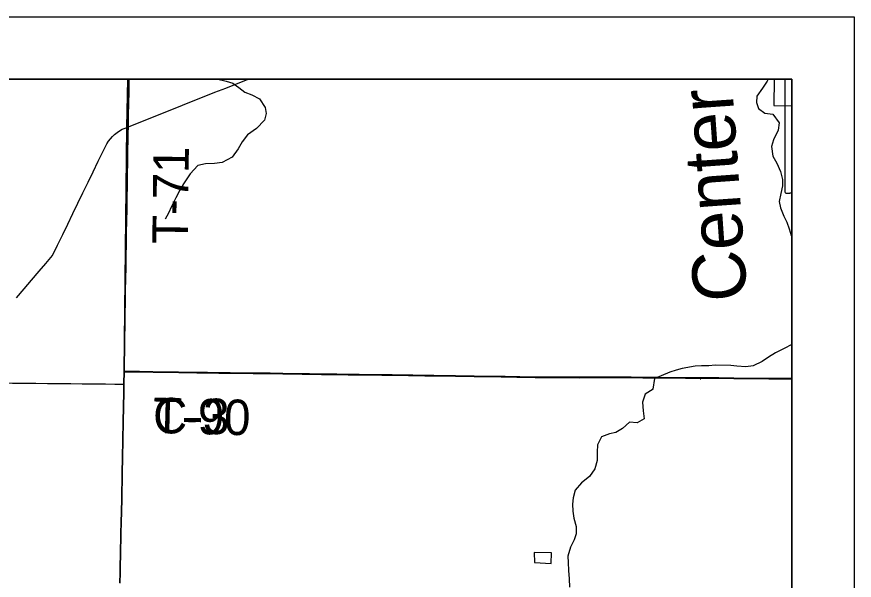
# Model space of a CAD drawing. Extents: x 0 to 34, y 0 to 22.
# Drawn here: x 7.658 to 9, y 20.097 to 21 of the extents above; entities that cross this region are included whole.
import ezdxf

# ---------------------------------------------------------------- set-up
doc = ezdxf.new("R2010")
doc.units = 0
for name, color, linetype in [('GM_X_Corporation', 7, 'Continuous'), ('GM_X_County_Road', 7, 'Continuous'), ('GM_X_County_Road_Text', 7, 'Continuous'), ('GM_X_Minor_Lake', 7, 'Continuous'), ('GM_X_Minor_River', 7, 'Continuous'), ('GM_X_Minor_River_Text', 7, 'Continuous'), ('GM_X_State_Shield', 7, 'Continuous'), ('GM_X_Township_Road', 7, 'Continuous'), ('GM_X_Township_Road_Text', 7, 'Continuous'), ('SH_Data', 7, 'Continuous')]:
    doc.layers.add(name, color=color, linetype=linetype)

msp = doc.modelspace()

# ---------------------------------------------------------------- linework, layer by layer
at = {"layer": 'GM_X_Corporation'}
for points in [[(7.8235, 20.0928), (7.8238, 20.1089), (7.8241, 20.1219), (7.8245, 20.1369), (7.825, 20.1729), (7.8253, 20.189), (7.8263, 20.2263), (7.827, 20.2692), (7.8275, 20.2934), (7.8288, 20.3506), (7.8296, 20.3984), (7.8298, 20.4118), (7.8301, 20.4313), (7.8546, 20.4315), (7.8763, 20.4311), (7.9174, 20.4306), (7.9465, 20.4301), (7.9639, 20.4298), (8, 20.4291), (8.0366, 20.4288), (8.064, 20.4286), (8.0845, 20.4283), (8.1274, 20.4276), (8.1709, 20.4271), (8.2069, 20.4266), (8.2597, 20.4261), (8.3262, 20.4252), (8.361, 20.4247), (8.3908, 20.4242), (8.4405, 20.4234), (8.4884, 20.4226), (8.5269, 20.4224), (8.5374, 20.4223), (8.5592, 20.4222), (8.5809, 20.4223), (8.6145, 20.4223), (8.6424, 20.4222), (8.7294, 20.4215), (8.7481, 20.4213), (8.7711, 20.4213), (8.7829, 20.4212), (8.8071, 20.421), (8.863, 20.4205), (8.8835, 20.4202), (8.9, 20.4201), (8.9, 20.9), (2.1, 20.9)], [(7.8235, 20.0928), (7.8238, 20.1089), (7.8241, 20.1219), (7.8245, 20.1369), (7.825, 20.1729), (7.8253, 20.189), (7.8263, 20.2263), (7.827, 20.2692), (7.8275, 20.2934), (7.8288, 20.3506), (7.8296, 20.3984), (7.8298, 20.4118), (7.8301, 20.4313), (7.8345, 20.8231), (7.8362, 20.9), (2.1, 20.9)], [(8.9, 14.1), (8.9, 20.4201), (8.8835, 20.4202), (8.863, 20.4205), (8.8071, 20.421), (8.7829, 20.4212), (8.7711, 20.4213), (8.7481, 20.4213), (8.7294, 20.4215), (8.6424, 20.4222), (8.6145, 20.4223), (8.5809, 20.4223), (8.5592, 20.4222), (8.5374, 20.4223), (8.5269, 20.4224), (8.4884, 20.4226), (8.4405, 20.4234), (8.3908, 20.4242), (8.361, 20.4247), (8.3262, 20.4252), (8.2597, 20.4261), (8.2069, 20.4266), (8.1709, 20.4271), (8.1274, 20.4276), (8.0845, 20.4283), (8.064, 20.4286), (8.0366, 20.4288), (8, 20.4291), (7.9639, 20.4298), (7.9465, 20.4301), (7.9174, 20.4306), (7.8763, 20.4311), (7.8546, 20.4315), (7.8301, 20.4313), (7.8298, 20.4118), (7.8296, 20.3984), (7.8288, 20.3506), (7.8275, 20.2934), (7.827, 20.2692), (7.8263, 20.2263), (7.8253, 20.189), (7.825, 20.1729), (7.8245, 20.1369), (7.8241, 20.1219), (7.8238, 20.1089), (7.8235, 20.0928)], [(8.9, 16.4207), (8.9, 20.4201), (8.8835, 20.4202), (8.863, 20.4205), (8.8071, 20.421), (8.7829, 20.4212), (8.7711, 20.4213), (8.7481, 20.4213), (8.7294, 20.4215), (8.6424, 20.4222), (8.6145, 20.4223), (8.5809, 20.4223), (8.5592, 20.4222), (8.5374, 20.4223), (8.5269, 20.4224), (8.4884, 20.4226), (8.4405, 20.4234), (8.3908, 20.4242), (8.361, 20.4247), (8.3262, 20.4252), (8.2597, 20.4261), (8.2069, 20.4266), (8.1709, 20.4271), (8.1274, 20.4276), (8.0845, 20.4283), (8.064, 20.4286), (8.0366, 20.4288), (8, 20.4291), (7.9639, 20.4298), (7.9465, 20.4301), (7.9174, 20.4306), (7.8763, 20.4311), (7.8546, 20.4315), (7.8301, 20.4313), (7.8298, 20.4118), (7.8296, 20.3984), (7.8288, 20.3506), (7.8275, 20.2934), (7.827, 20.2692), (7.8263, 20.2263), (7.8253, 20.189), (7.825, 20.1729), (7.8245, 20.1369), (7.8241, 20.1219), (7.8238, 20.1089), (7.8235, 20.0928)]]:
    msp.add_lwpolyline(points, dxfattribs=at)
for points in [[(8.9, 20.4201), (8.9, 20.9), (7.8362, 20.9), (7.8345, 20.8231), (7.8301, 20.4313), (7.8546, 20.4315), (7.8763, 20.4311), (7.9174, 20.4306), (7.9465, 20.4301), (7.9639, 20.4298), (8, 20.4291), (8.0366, 20.4288), (8.064, 20.4286), (8.0845, 20.4283), (8.1274, 20.4276), (8.1709, 20.4271), (8.2069, 20.4266), (8.2597, 20.4261), (8.3262, 20.4252), (8.361, 20.4247), (8.3908, 20.4242), (8.4405, 20.4234), (8.4884, 20.4226), (8.5269, 20.4224), (8.5374, 20.4223), (8.5592, 20.4222), (8.5809, 20.4223), (8.6145, 20.4223), (8.6424, 20.4222), (8.7294, 20.4215), (8.7481, 20.4213), (8.7711, 20.4213), (8.7829, 20.4212), (8.8071, 20.421), (8.863, 20.4205), (8.8835, 20.4202)], [(8.9, 20.8573), (8.9, 20.9), (8.8716, 20.9), (8.8709, 20.8576)]]:
    msp.add_lwpolyline(points, close=True, dxfattribs=at)
at = {"layer": 'GM_X_County_Road'}
msp.add_line((8.391, 20.4237), (8.4091, 20.4234), dxfattribs=at)
for points in [[(7.8371, 20.8238), (7.8544, 20.8307), (7.8717, 20.8376), (7.889, 20.8444), (7.9064, 20.8513), (7.9237, 20.8582), (7.941, 20.8651), (7.9583, 20.872), (7.9756, 20.8789), (7.9929, 20.8858), (8.0103, 20.8927), (8.0276, 20.8996), (8.0286, 20.9)], [(7.6577, 20.5497), (7.6698, 20.5639), (7.6819, 20.578), (7.694, 20.5922), (7.7048, 20.6048), (7.7155, 20.6174), (7.7237, 20.6341), (7.7318, 20.6509), (7.7399, 20.6677), (7.748, 20.6845), (7.7561, 20.7012), (7.7643, 20.718), (7.7724, 20.7348), (7.7805, 20.7516), (7.7886, 20.7684), (7.7944, 20.7803), (7.8002, 20.7922), (7.8025, 20.7965), (7.8051, 20.8007), (7.8081, 20.8046), (7.8114, 20.8082), (7.815, 20.8115), (7.8189, 20.8146), (7.823, 20.8173), (7.8273, 20.8197), (7.8318, 20.8217), (7.8371, 20.8238)], [(7.8301, 20.4113), (7.8302, 20.421), (7.8304, 20.4307)], [(7.8304, 20.4307), (7.8548, 20.4309), (7.8657, 20.4307), (7.8766, 20.4305), (7.9064, 20.4302), (7.9176, 20.4301), (7.9322, 20.4298), (7.9468, 20.4295), (7.9642, 20.4293), (7.9822, 20.4289), (8.0002, 20.4286), (8.0369, 20.4283), (8.0505, 20.4282), (8.0642, 20.4281), (8.0847, 20.4277), (8.1034, 20.4275), (8.1155, 20.4273), (8.1276, 20.4271), (8.1462, 20.4269), (8.1587, 20.4267), (8.1711, 20.4266), (8.1891, 20.4263), (8.2071, 20.4261), (8.2258, 20.4259), (8.2429, 20.4257), (8.2599, 20.4255), (8.3118, 20.4248), (8.3438, 20.4244), (8.3612, 20.4241), (8.391, 20.4237)], [(8.4091, 20.4234), (8.4594, 20.4226), (8.474, 20.4223), (8.4886, 20.4221), (8.5072, 20.422), (8.5172, 20.4219), (8.5377, 20.4218), (8.5485, 20.4217), (8.5594, 20.4216), (8.5811, 20.4218), (8.6613, 20.4215), (8.6986, 20.4212), (8.7297, 20.421), (8.7483, 20.4208), (8.7831, 20.4207), (8.8073, 20.4204), (8.8446, 20.4201), (8.8632, 20.4199), (8.8837, 20.4197), (8.9, 20.4196)], [(7.8238, 20.0922), (7.8241, 20.1084), (7.8244, 20.1214), (7.8247, 20.1363), (7.825, 20.1543), (7.8252, 20.1724), (7.8255, 20.1885), (7.8261, 20.2071), (7.8263, 20.2164), (7.8266, 20.2258), (7.8273, 20.2687), (7.8277, 20.2929), (7.8282, 20.3115), (7.8286, 20.3301), (7.829, 20.35), (7.8293, 20.3687), (7.8296, 20.3833), (7.8298, 20.3979), (7.8301, 20.4113)]]:
    msp.add_lwpolyline(points, dxfattribs=at)
at = {"layer": 'GM_X_Minor_Lake'}
for points in [[(8.5149, 20.1407), (8.487, 20.1412), (8.4877, 20.1252)], [(8.4877, 20.1252), (8.5145, 20.1239), (8.5149, 20.1407), (8.5149, 20.1407)]]:
    msp.add_lwpolyline(points, dxfattribs=at)
at = {"layer": 'GM_X_Minor_River'}
msp.add_line((8.6778, 20.403), (8.6806, 20.4203), dxfattribs=at)
for points in [[(7.9788, 20.9), (7.9803, 20.8999), (7.9939, 20.8965), (8.0041, 20.8936), (8.0141, 20.8865), (8.0238, 20.879), (8.0347, 20.8749), (8.047, 20.8682), (8.0562, 20.8543), (8.0578, 20.8447), (8.0549, 20.8342), (8.0424, 20.8208), (8.0277, 20.811), (8.0194, 20.7998), (8.0127, 20.7882), (8.0032, 20.7748), (7.9874, 20.7665), (7.9749, 20.7649), (7.9608, 20.7645), (7.9482, 20.7618), (7.9361, 20.7485), (7.9251, 20.7324), (7.9195, 20.722), (7.9131, 20.7096), (7.9063, 20.6961), (7.9011, 20.6853), (7.8959, 20.6755)], [(8.8623, 20.9), (8.8605, 20.8968), (8.8529, 20.8856), (8.8439, 20.8726), (8.8432, 20.8627), (8.8464, 20.8532), (8.8568, 20.8457), (8.8697, 20.8438), (8.8799, 20.8299), (8.8781, 20.8182), (8.8705, 20.8025), (8.8675, 20.7923), (8.8698, 20.7767), (8.8759, 20.7651), (8.882, 20.7521), (8.8851, 20.7391), (8.8852, 20.7288), (8.8826, 20.7168), (8.8796, 20.7039), (8.882, 20.6936), (8.8874, 20.6806), (8.892, 20.6706), (8.8959, 20.6603), (8.899, 20.6492), (8.9, 20.6453)], [(8.9, 20.475), (8.8878, 20.4685), (8.8736, 20.4612), (8.8628, 20.4547), (8.8523, 20.4474), (8.8378, 20.4405), (8.8263, 20.4389), (8.8119, 20.44), (8.8021, 20.4411), (8.7771, 20.4417), (8.7668, 20.4408), (8.7554, 20.4407), (8.7452, 20.4399), (8.7242, 20.4362), (8.7147, 20.4338), (8.7043, 20.4303), (8.6806, 20.4201)], [(8.754, 20.4193), (8.7533, 20.4191)], [(8.6778, 20.403), (8.6651, 20.3952), (8.661, 20.3824), (8.6619, 20.3687), (8.6632, 20.3557), (8.6524, 20.3495), (8.6398, 20.3505), (8.6285, 20.3404), (8.6181, 20.3338), (8.6081, 20.3317), (8.5951, 20.327), (8.5884, 20.3142), (8.5881, 20.3024), (8.5883, 20.2891), (8.5846, 20.2755), (8.5759, 20.2635), (8.5628, 20.2531), (8.553, 20.2411), (8.5497, 20.229), (8.5488, 20.2191), (8.5493, 20.2077), (8.5506, 20.1963), (8.5546, 20.1829), (8.5547, 20.1715), (8.5511, 20.1616), (8.5456, 20.15), (8.5411, 20.1356), (8.5417, 20.1253), (8.5422, 20.1124), (8.5435, 20.0994), (8.544, 20.0857)]]:
    msp.add_lwpolyline(points, dxfattribs=at)
at = {"layer": 'GM_X_State_Shield'}
msp.add_lwpolyline([(8.9, 20.717), (8.9, 20.9), (8.8889, 20.9), (8.8889, 20.7206)], dxfattribs=at)
for centre, radius, start, end in [((8.892, 20.7201), 0.00308, 171.4911, 258.3065), ((8.8925, 20.7406), 0.0235, 267.339, 280.6039), ((8.8973, 20.709), 0.00848, 71.2569, 93.2717)]:
    msp.add_arc(centre, radius, start, end, dxfattribs=at)
at = {"layer": 'GM_X_Township_Road'}
msp.add_line((8.391, 20.4237), (8.4091, 20.4234), dxfattribs=at)
for points in [[(7.8304, 20.4307), (7.8307, 20.4494), (7.831, 20.468), (7.8313, 20.4867), (7.8316, 20.5053), (7.832, 20.5239), (7.8323, 20.5426), (7.8326, 20.5612), (7.8329, 20.5799), (7.8332, 20.5985), (7.8336, 20.6171), (7.8339, 20.6358), (7.8342, 20.6544), (7.8345, 20.6731), (7.8348, 20.6917), (7.8351, 20.7104), (7.8355, 20.729), (7.8358, 20.7476), (7.8361, 20.7663), (7.8364, 20.7849), (7.8367, 20.8036), (7.8369, 20.8137), (7.8371, 20.8238), (7.8374, 20.8424), (7.8377, 20.8611), (7.8381, 20.8797), (7.8384, 20.897), (7.8384, 20.9)], [(7.8301, 20.4113), (7.8302, 20.421), (7.8304, 20.4307)], [(7.8304, 20.4307), (7.8548, 20.4309), (7.8657, 20.4307), (7.8766, 20.4305), (7.9064, 20.4302), (7.9176, 20.4301), (7.9322, 20.4298), (7.9468, 20.4295), (7.9642, 20.4293), (7.9822, 20.4289), (8.0002, 20.4286), (8.0369, 20.4283), (8.0505, 20.4282), (8.0642, 20.4281), (8.0847, 20.4277), (8.1034, 20.4275), (8.1155, 20.4273), (8.1276, 20.4271), (8.1462, 20.4269), (8.1587, 20.4267), (8.1711, 20.4266), (8.1891, 20.4263), (8.2071, 20.4261), (8.2258, 20.4259), (8.2429, 20.4257), (8.2599, 20.4255), (8.3118, 20.4248), (8.3438, 20.4244), (8.3612, 20.4241), (8.391, 20.4237)], [(8.4091, 20.4234), (8.4594, 20.4226), (8.474, 20.4223), (8.4886, 20.4221), (8.5072, 20.422), (8.5172, 20.4219), (8.5377, 20.4218), (8.5485, 20.4217), (8.5594, 20.4216), (8.5811, 20.4218), (8.6613, 20.4215), (8.6986, 20.4212), (8.7297, 20.421), (8.7483, 20.4208), (8.7831, 20.4207), (8.8073, 20.4204), (8.8446, 20.4201), (8.8632, 20.4199), (8.8837, 20.4197), (8.9, 20.4196)], [(7.5413, 20.4141), (7.5591, 20.4139), (7.5768, 20.4137), (7.5955, 20.4135), (7.6141, 20.4133), (7.6327, 20.4132), (7.6514, 20.413), (7.67, 20.4128), (7.6887, 20.4126), (7.7073, 20.4125), (7.7259, 20.4123), (7.7446, 20.4121), (7.7632, 20.4119), (7.7819, 20.4117), (7.8005, 20.4116), (7.8153, 20.4114), (7.8301, 20.4113)], [(7.8238, 20.0922), (7.8241, 20.1084), (7.8244, 20.1214), (7.8247, 20.1363), (7.825, 20.1543), (7.8252, 20.1724), (7.8255, 20.1885), (7.8261, 20.2071), (7.8263, 20.2164), (7.8266, 20.2258), (7.8273, 20.2687), (7.8277, 20.2929), (7.8282, 20.3115), (7.8286, 20.3301), (7.829, 20.35), (7.8293, 20.3687), (7.8296, 20.3833), (7.8298, 20.3979), (7.8301, 20.4113)]]:
    msp.add_lwpolyline(points, dxfattribs=at)
at = {"layer": 'SH_Data'}
for p, q in [((2, 21), (9, 21)), ((9, 21), (9, 14)), ((2.1, 20.9), (8.9, 20.9)), ((2.1, 20.9), (8.9, 20.9)), ((8.9, 20.9), (8.9, 14.1)), ((8.9, 20.9), (8.9, 14.1))]:
    msp.add_line(p, q, dxfattribs=at)

# ---------------------------------------------------------------- texts
at = {"layer": 'GM_X_County_Road_Text'}
msp.add_text('C-3', height=0.05682, rotation=359.0877, dxfattribs=at).set_placement((7.8761, 20.3328))
at = {"layer": 'GM_X_Minor_River_Text'}
msp.add_text('Center', height=0.08523, rotation=94.0336, dxfattribs=at).set_placement((8.8288, 20.5464))
at = {"layer": 'GM_X_Township_Road_Text'}
for s, rotation, p in [('T-71', 89.2924, (7.9321, 20.6354)), ('T-90', 358.5868, (7.8758, 20.333))]:
    msp.add_text(s, height=0.05682, rotation=rotation, dxfattribs=at).set_placement(p)

doc.saveas('drawing.dxf')
